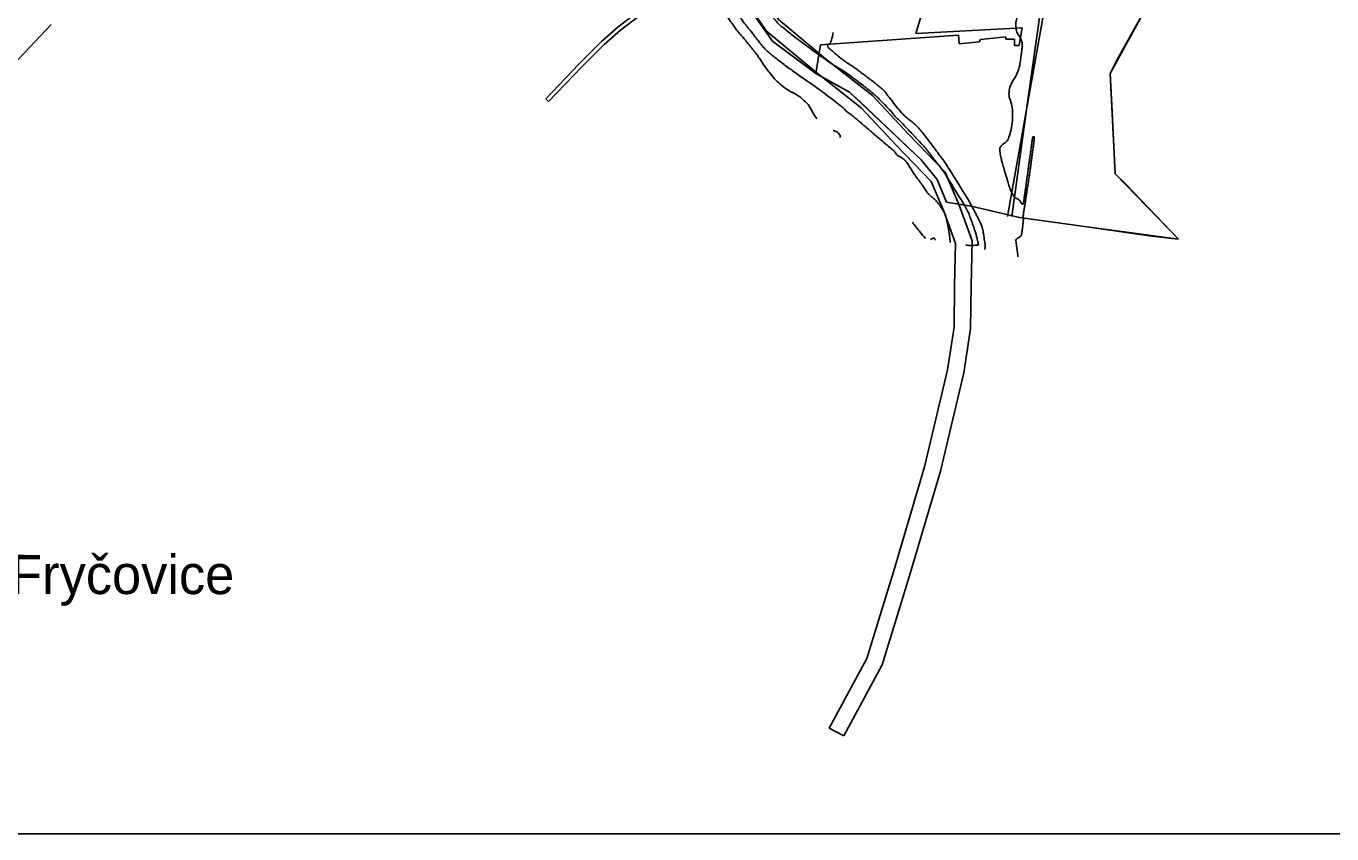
# Model space of a CAD drawing. Extents: x -478495 to -472450, y -1118050 to -1113745.
# Drawn here: x -476461 to -475794, y -1118000 to -1117588 of the extents above; entities that cross this region are included whole.
import ezdxf

# ---------------------------------------------------------------- set-up
doc = ezdxf.new("R2010")
doc.units = 0
for name, color, linetype in [('cyklostezka', 7, 'Continuous'), ('el vedeni_VVN', 7, 'Continuous'), ('hranice kú', 7, 'Continuous'), ('Implicitní', 7, 'Continuous'), ('nesmenovane pozemky', 7, 'Continuous'), ('ObPÚ', 7, 'Continuous'), ('okolní k_ú_', 7, 'Continuous'), ('silnice', 7, 'Continuous'), ('vodní plochy', 7, 'Continuous'), ('Vrstevnice_hlavni', 7, 'Continuous'), ('Vrstevnice_vedlejsi', 7, 'Continuous')]:
    doc.layers.add(name, color=color, linetype=linetype)

msp = doc.modelspace()

# ---------------------------------------------------------------- linework, layer by layer
at = {"layer": 'cyklostezka'}
msp.add_lwpolyline([(-476254.27, -1116156.47), (-476222.18, -1116232.89), (-476211.78, -1116254.37), (-476202.07, -1116276.08), (-476175.63, -1116319.27), (-476155.29, -1116349.34), (-476145.57, -1116374.89), (-476134.72, -1116405.19), (-476127.72, -1116444.76), (-476107.83, -1116579.35), (-476095.96, -1116657.36), (-476085.23, -1116737.63), (-476059.24, -1116863.13), (-475998.22, -1117016.88), (-475935.51, -1117171.2), (-475924.21, -1117200.03), (-475907.82, -1117246.95), (-475900.14, -1117263), (-475894.04, -1117290.14), (-475894.94, -1117318.4), (-475960.16, -1117684.94)], dxfattribs=at)
at = {"layer": 'el vedeni_VVN'}
msp.add_line((-476448.36, -1117586.8), (-476554.56, -1117699.16), dxfattribs=at)
at = {"layer": 'hranice kú'}
for p, q in [((-476100.96, -1117565.49), (-476080.12, -1117595.42)), ((-475907.68, -1117611.89), (-475884.68, -1117569.79)), ((-476080.12, -1117595.42), (-476057.93, -1117611.9)), ((-476057.93, -1117611.9), (-476054.39, -1117613.81)), ((-476054.39, -1117613.81), (-476051.06, -1117615.71)), ((-476051.06, -1117615.71), (-476048.51, -1117617.05)), ((-476048.51, -1117617.05), (-476046.35, -1117618.3)), ((-475905.17, -1117663.11), (-475907.68, -1117611.89)), ((-476046.35, -1117618.3), (-476043.47, -1117619.85)), ((-476043.47, -1117619.85), (-476040.79, -1117621.32)), ((-476040.79, -1117621.32), (-476035.44, -1117626.13)), ((-476035.44, -1117626.13), (-476004.15, -1117655.95)), ((-476004.15, -1117655.95), (-475996.04, -1117665.9)), ((-475872.79, -1117696.45), (-475905.17, -1117663.11)), ((-475996.04, -1117665.9), (-475991.21, -1117677.58)), ((-475991.21, -1117677.58), (-475978.66, -1117679.6)), ((-475978.66, -1117679.6), (-475953.91, -1117685.39)), ((-475953.91, -1117685.39), (-475920.81, -1117690.04)), ((-475920.81, -1117690.04), (-475872.79, -1117696.45))]:
    msp.add_line(p, q, dxfattribs=at)
at = {"layer": 'Implicitní'}
msp.add_lwpolyline([(-472500.13, -1113795.05), (-472500.13, -1118000.05), (-478445.13, -1118000.05), (-478445.13, -1113795.05)], close=True, dxfattribs=at)
at = {"layer": 'nesmenovane pozemky'}
for p, q in [((-475903.65, -1117603.88), (-475884.68, -1117569.79)), ((-476001.83, -1117574.47), (-476006.93, -1117591.35)), ((-476006.93, -1117591.35), (-475974.97, -1117589.77)), ((-475974.97, -1117589.77), (-475952.65, -1117588.52)), ((-475952.65, -1117588.52), (-475954.12, -1117597.47)), ((-476055.59, -1117597.25), (-476057.93, -1117611.9)), ((-475985.18, -1117592.28), (-476055.59, -1117597.25)), ((-475984.86, -1117596.73), (-475985.18, -1117592.28)), ((-475974.6, -1117595.69), (-475984.86, -1117596.73)), ((-475973.88, -1117594.46), (-475974.6, -1117595.69)), ((-475960.87, -1117593.11), (-475973.88, -1117594.46)), ((-475960.87, -1117594.38), (-475960.87, -1117593.11)), ((-475956.57, -1117594.38), (-475960.87, -1117594.38)), ((-475956.57, -1117597.47), (-475956.57, -1117594.38)), ((-475954.12, -1117597.47), (-475956.57, -1117597.47)), ((-475907.68, -1117611.89), (-475903.65, -1117603.88)), ((-476057.93, -1117611.9), (-476040.79, -1117621.32)), ((-475906.89, -1117627.99), (-475907.68, -1117611.89)), ((-476040.79, -1117621.32), (-476004.15, -1117655.95)), ((-475905.17, -1117663.11), (-475906.89, -1117627.99)), ((-476004.15, -1117655.95), (-475996.04, -1117665.9)), ((-475899.66, -1117668.27), (-475905.17, -1117663.11)), ((-475996.04, -1117665.9), (-475991.21, -1117677.58)), ((-475872.79, -1117696.45), (-475899.66, -1117668.27)), ((-475991.21, -1117677.58), (-475978.66, -1117679.6)), ((-475978.66, -1117679.6), (-475966.28, -1117682.49)), ((-475966.28, -1117682.49), (-475953.91, -1117685.39)), ((-475953.91, -1117685.39), (-475920.81, -1117690.04)), ((-475920.81, -1117690.04), (-475886.4, -1117694.96)), ((-475886.4, -1117694.96), (-475872.79, -1117696.45))]:
    msp.add_line(p, q, dxfattribs=at)
at = {"layer": 'ObPÚ'}
for p, q in [((-476100.96, -1117565.49), (-476080.12, -1117595.42)), ((-476006.93, -1117591.35), (-476001.83, -1117574.47)), ((-475974.97, -1117589.77), (-476006.93, -1117591.35)), ((-475952.65, -1117588.52), (-475974.97, -1117589.77)), ((-475954.12, -1117597.47), (-475952.65, -1117588.52)), ((-476080.12, -1117595.42), (-476057.93, -1117611.9)), ((-476057.93, -1117611.9), (-476055.59, -1117597.25)), ((-476055.59, -1117597.25), (-475985.18, -1117592.28)), ((-475985.18, -1117592.28), (-475984.86, -1117596.73)), ((-475984.86, -1117596.73), (-475974.6, -1117595.69)), ((-475974.6, -1117595.69), (-475973.88, -1117594.46)), ((-475973.88, -1117594.46), (-475960.87, -1117593.11)), ((-475960.87, -1117593.11), (-475960.87, -1117594.38)), ((-475960.87, -1117594.38), (-475956.57, -1117594.38)), ((-475956.57, -1117594.38), (-475956.57, -1117597.47)), ((-475956.57, -1117597.47), (-475954.12, -1117597.47))]:
    msp.add_line(p, q, dxfattribs=at)
at = {"layer": 'silnice'}
msp.add_lwpolyline([(-475957.9, -1117684.78), (-475949.88, -1117626.62), (-475938.63, -1117546.98), (-475927.03, -1117479.27), (-475917.65, -1117429.3), (-475903.98, -1117378.32)], dxfattribs=at)
at = {"layer": 'vodní plochy'}
for p, q in [((-476195.86, -1117624.84), (-476194.41, -1117626.22)), ((-476051.11, -1117946.05), (-476043.66, -1117950.07)), ((-476051.11, -1117946.05), (-476043.66, -1117950.07))]:
    msp.add_line(p, q, dxfattribs=at)
for points in [[(-476156.31, -1117361.66), (-476163.99, -1117375.67), (-476163.99, -1117389.9), (-476152.92, -1117410.92), (-476142.3, -1117430.6), (-476130.77, -1117459.77), (-476124.44, -1117494.59), (-476117.77, -1117517.88), (-476114.89, -1117528.18), (-476108.17, -1117553.38), (-476083.32, -1117590), (-476058.35, -1117610.85), (-476034.84, -1117629.4), (-476016.76, -1117648.62), (-475999.13, -1117666.94), (-475992.57, -1117682.09), (-475986.7, -1117698.61), (-475987.15, -1117720.09), (-475987.37, -1117741.29), (-475990.76, -1117763.06), (-476002.52, -1117812.64), (-476018.34, -1117866.34), (-476031.9, -1117910.44), (-476051.11, -1117946.05)], [(-476043.66, -1117950.07), (-476024.06, -1117913.72), (-476010.24, -1117868.78), (-475994.34, -1117814.81), (-475982.46, -1117764.69), (-475978.92, -1117741.99), (-475978.69, -1117720.23), (-475978.21, -1117697.23), (-475984.7, -1117678.99), (-475991.98, -1117662.17), (-476010.63, -1117642.79), (-476029.11, -1117623.14), (-476053.02, -1117604.29), (-476076.98, -1117584.27), (-476100.37, -1117549.81), (-476106.73, -1117525.94), (-476109.64, -1117515.58), (-476116.19, -1117492.67), (-476122.6, -1117457.44), (-476134.62, -1117427.02), (-476145.46, -1117406.94), (-476155.53, -1117387.81), (-476155.53, -1117377.84), (-476148.69, -1117365.34)], [(-476194.41, -1117626.22), (-476177.46, -1117608.42), (-476166.03, -1117596.98), (-476157.76, -1117589.75), (-476151.15, -1117584.76), (-476148.59, -1117582.97), (-476108.75, -1117557.22), (-476106.47, -1117555.89)], [(-476109.8, -1117555.52), (-476149.7, -1117581.31), (-476152.33, -1117583.15), (-476159.02, -1117588.2), (-476167.39, -1117595.52), (-476178.89, -1117607.02)], [(-476178.89, -1117607.02), (-476195.86, -1117624.84)]]:
    msp.add_lwpolyline(points, dxfattribs=at)
at = {"layer": 'Vrstevnice_hlavni'}
for points in [[(-476057.44, -1117634.99), (-476057.69, -1117634.62), (-476059.41, -1117631.91), (-476061.34, -1117628.56), (-476064.03, -1117625.55), (-476067.48, -1117622.88), (-476071.7, -1117620.54), (-476075.34, -1117618), (-476078.42, -1117615.24), (-476080.92, -1117612.27), (-476083.06, -1117609.55), (-476084.83, -1117607.08), (-476086.23, -1117604.87), (-476087.53, -1117602.95), (-476088.72, -1117601.3), (-476089.82, -1117599.94), (-476090.61, -1117598.96), (-476091.09, -1117598.37), (-476091.25, -1117598.16), (-476092.2, -1117597.01), (-476093.93, -1117594.91), (-476096.46, -1117591.87), (-476098.15, -1117589.84), (-476099, -1117588.82), (-476099.01, -1117588.81), (-476099.33, -1117588.34), (-476099.98, -1117587.41), (-476100.95, -1117586.02), (-476102.07, -1117584.42), (-476103.34, -1117582.61), (-476104.78, -1117580.59), (-476106.25, -1117578.08), (-476107.76, -1117575.09), (-476109.3, -1117571.6), (-476110.35, -1117569.23), (-476110.9, -1117567.98), (-476110.95, -1117567.84), (-476111.6, -1117566.05), (-476112.86, -1117562.6), (-476114.73, -1117557.5), (-476116.04, -1117553.98), (-476116.81, -1117552.04), (-476117.02, -1117551.7), (-476117.64, -1117551.15), (-476118.66, -1117550.38), (-476120.08, -1117549.41), (-476123.25, -1117546.64), (-476128.16, -1117542.06), (-476134.81, -1117535.69), (-476139.46, -1117531.05), (-476142.12, -1117528.16), (-476142.79, -1117527), (-476143.3, -1117525.93), (-476143.66, -1117524.93), (-476143.86, -1117524), (-476144.67, -1117522.64), (-476146.08, -1117520.86), (-476148.09, -1117518.64), (-476149.82, -1117516.46), (-476151.26, -1117514.3), (-476152.42, -1117512.19), (-476153.15, -1117510.07), (-476153.47, -1117507.95), (-476153.36, -1117505.83), (-476153.29, -1117504.29), (-476153.27, -1117503.33), (-476153.29, -1117502.96), (-476153.96, -1117501.7), (-476155.3, -1117499.55), (-476157.29, -1117496.52), (-476158.79, -1117493.8), (-476159.79, -1117491.38), (-476160.29, -1117489.27), (-476160.62, -1117487.82), (-476160.79, -1117487.03), (-476160.79, -1117486.91), (-476160.79, -1117486.8), (-476160.8, -1117486.7), (-476160.81, -1117486.6), (-476161.22, -1117484.01), (-476162.05, -1117478.92), (-476163.28, -1117471.34), (-476164.14, -1117466.2), (-476164.63, -1117463.5)], [(-475971.72, -1117701.76), (-475971.61, -1117701.25), (-475971.59, -1117698.98), (-475972.08, -1117695.56), (-475972.45, -1117693.12), (-475972.7, -1117691.67), (-475972.81, -1117691.21), (-475972.99, -1117690.62), (-475973.23, -1117689.89), (-475973.54, -1117689.03), (-475974.41, -1117687.19), (-475975.85, -1117684.36), (-475977.85, -1117680.54), (-475979.53, -1117677.45), (-475980.88, -1117675.08), (-475981.89, -1117673.43), (-475983.61, -1117670.66), (-475986.04, -1117666.77), (-475989.16, -1117661.77), (-475991.49, -1117658.11), (-475993.04, -1117655.8), (-475993.79, -1117654.84), (-475995.3, -1117652.83), (-475997.59, -1117649.79), (-476000.64, -1117645.7), (-476003.17, -1117642.45), (-476005.19, -1117640.03), (-476006.69, -1117638.45), (-476008.27, -1117636.98), (-476009.95, -1117635.61), (-476011.71, -1117634.35), (-476013.98, -1117632.09), (-476016.75, -1117628.84), (-476020.03, -1117624.6), (-476022.23, -1117621.76), (-476023.34, -1117620.33), (-476023.37, -1117620.3), (-476023.49, -1117620.2), (-476023.71, -1117620.02), (-476024.04, -1117619.76), (-476024.78, -1117619.16), (-476025.93, -1117618.22), (-476027.51, -1117616.94), (-476029.12, -1117615.67), (-476030.75, -1117614.42), (-476032.42, -1117613.2), (-476034.1, -1117611.94), (-476035.81, -1117610.66), (-476037.54, -1117609.35), (-476039.11, -1117608.23), (-476040.54, -1117607.3), (-476041.81, -1117606.55), (-476043.59, -1117605.28), (-476045.89, -1117603.5), (-476048.69, -1117601.2), (-476050.65, -1117599.46), (-476051.75, -1117598.28), (-476051.99, -1117597.66), (-476051.96, -1117597.21), (-476051.64, -1117596.93), (-476051.05, -1117596.82), (-476050.5, -1117596.11), (-476050, -1117594.79), (-476049.09, -1117590.93)], [(-476045.37, -1117644.51), (-476045.96, -1117642.83), (-476047.71, -1117641.43), (-476049.11, -1117640.97)], [(-476008.67, -1117687.7), (-476004.74, -1117692.89), (-476001.98, -1117696.1)], [(-475999.44, -1117696.51), (-475998.68, -1117696.34), (-475997.53, -1117695.86), (-475997.03, -1117696.9)]]:
    msp.add_spline(points, degree=3, dxfattribs=at)
at = {"layer": 'Vrstevnice_vedlejsi'}
for points in [[(-475925.81, -1117448.34), (-475926.27, -1117450.62), (-475926.74, -1117453.03), (-475927.22, -1117455.56), (-475927.71, -1117458.22), (-475928.12, -1117460.4), (-475928.45, -1117462.08), (-475928.7, -1117463.29), (-475929.01, -1117464.76), (-475929.38, -1117466.49), (-475929.8, -1117468.49), (-475930.15, -1117470.18), (-475930.42, -1117471.57), (-475930.61, -1117472.66), (-475930.86, -1117474.2), (-475931.19, -1117476.21), (-475931.59, -1117478.69), (-475931.91, -1117480.67), (-475932.15, -1117482.18), (-475932.32, -1117483.2), (-475932.51, -1117484.34), (-475932.72, -1117485.59), (-475932.95, -1117486.96), (-475933.17, -1117488.18), (-475933.37, -1117489.26), (-475933.56, -1117490.19), (-475933.78, -1117491.18), (-475934.02, -1117492.24), (-475934.28, -1117493.36), (-475934.52, -1117494.24), (-475934.72, -1117494.87), (-475934.9, -1117495.27), (-475935.04, -1117495.61), (-475935.16, -1117495.89), (-475935.25, -1117496.11), (-475935.32, -1117496.27), (-475935.37, -1117496.37), (-475935.39, -1117496.39), (-475935.35, -1117496.51), (-475935.25, -1117496.71), (-475935.1, -1117496.99), (-475935.1, -1117497.4), (-475935.26, -1117497.94), (-475935.58, -1117498.61), (-475935.96, -1117499.97), (-475936.41, -1117502.02), (-475936.93, -1117504.77), (-475937.64, -1117508.89), (-475938.52, -1117514.38), (-475939.59, -1117521.24), (-475940.34, -1117526), (-475940.78, -1117528.65), (-475940.89, -1117529.2), (-475940.96, -1117529.61), (-475940.99, -1117529.88), (-475940.98, -1117530.01), (-475940.98, -1117530.14), (-475940.97, -1117530.29), (-475940.96, -1117530.45), (-475940.99, -1117530.58), (-475941.07, -1117530.68), (-475941.18, -1117530.75), (-475941.38, -1117530.99), (-475941.66, -1117531.39), (-475942.02, -1117531.94), (-475942.31, -1117532.51), (-475942.53, -1117533.08), (-475942.67, -1117533.66), (-475942.83, -1117534.11), (-475942.99, -1117534.43), (-475943.17, -1117534.61), (-475943.26, -1117535.05), (-475943.26, -1117535.75), (-475943.17, -1117536.69), (-475943.05, -1117537.53), (-475942.91, -1117538.26), (-475942.74, -1117538.88), (-475942.67, -1117539.51), (-475942.7, -1117540.14), (-475942.83, -1117540.77), (-475943.25, -1117541.79), (-475943.98, -1117543.19), (-475945.01, -1117544.99), (-475946.02, -1117548.38), (-475947.02, -1117553.37), (-475948.01, -1117559.96), (-475949.32, -1117565.97), (-475950.93, -1117571.41), (-475952.87, -1117576.28), (-475954.34, -1117580.4), (-475955.34, -1117583.76), (-475955.87, -1117586.39), (-475955.76, -1117588.89), (-475955.01, -1117591.29), (-475953.62, -1117593.56), (-475952.78, -1117595.73), (-475952.5, -1117597.78)], [(-475981.46, -1117699.48), (-475978.55, -1117699.62), (-475976.13, -1117699.56), (-475974.95, -1117699.27), (-475975.03, -1117698.75), (-475975.23, -1117697.81), (-475975.55, -1117696.45), (-475975.99, -1117694.67), (-475976.68, -1117692.38), (-475977.61, -1117689.58), (-475978.79, -1117686.27), (-475979.74, -1117683.74), (-475980.47, -1117682), (-475980.98, -1117681.04), (-475982.27, -1117678.84), (-475984.36, -1117675.4), (-475987.25, -1117670.73), (-475989.48, -1117667.11), (-475991.07, -1117664.55), (-475992, -1117663.05), (-475993.33, -1117661.15), (-475995.07, -1117658.83), (-475997.2, -1117656.1), (-475998.94, -1117653.86), (-476000.28, -1117652.11), (-476001.22, -1117650.84), (-476003.36, -1117648.41), (-476006.69, -1117644.82), (-476011.21, -1117640.06), (-476014.37, -1117636.77), (-476016.19, -1117634.96), (-476016.65, -1117634.63), (-476017.25, -1117634.03), (-476017.99, -1117633.17), (-476018.85, -1117632.05), (-476020.29, -1117630.42), (-476022.3, -1117628.27), (-476024.89, -1117625.61), (-476027.16, -1117623.4), (-476029.12, -1117621.64), (-476030.78, -1117620.32), (-476033, -1117618.59), (-476035.8, -1117616.45), (-476039.17, -1117613.88), (-476042.25, -1117611.68), (-476045.04, -1117609.83), (-476047.54, -1117608.35), (-476050.58, -1117606.37), (-476054.16, -1117603.91), (-476058.28, -1117600.96), (-476062.21, -1117598.08), (-476065.95, -1117595.28), (-476069.5, -1117592.56), (-476072.06, -1117590.57), (-476073.62, -1117589.31), (-476074.19, -1117588.79), (-476074.68, -1117588.4), (-476075.1, -1117588.15), (-476075.44, -1117588.03), (-476076.24, -1117587.3), (-476077.5, -1117585.94), (-476079.22, -1117583.96), (-476080.45, -1117582.53), (-476081.17, -1117581.65), (-476081.4, -1117581.33), (-476081.7, -1117580.86), (-476082.07, -1117580.26), (-476082.53, -1117579.52), (-476083.53, -1117577.81), (-476085.07, -1117575.13), (-476087.16, -1117571.49), (-476088.85, -1117568.53), (-476090.14, -1117566.24), (-476091.03, -1117564.64), (-476092.06, -1117562.71), (-476093.26, -1117560.45), (-476094.6, -1117557.85), (-476095.62, -1117555.79), (-476096.3, -1117554.27), (-476096.66, -1117553.27), (-476097.35, -1117551.32), (-476098.38, -1117548.41), (-476099.75, -1117544.54), (-476100.77, -1117541.59), (-476101.44, -1117539.54), (-476101.76, -1117538.4), (-476102.23, -1117536.61), (-476102.85, -1117534.18), (-476103.61, -1117531.1), (-476104.48, -1117527.46), (-476105.44, -1117523.26)], [(-476106.82, -1117565.14), (-476105.77, -1117567.12), (-476104.85, -1117568.95), (-476104.06, -1117570.62), (-476103.42, -1117572.13), (-476102.76, -1117573.35), (-476102.11, -1117574.28), (-476101.45, -1117574.92), (-476100.89, -1117575.71), (-476100.42, -1117576.65), (-476100.04, -1117577.74), (-476099.46, -1117578.95), (-476098.67, -1117580.27), (-476097.67, -1117581.71), (-476096.76, -1117583), (-476095.95, -1117584.16), (-476095.22, -1117585.18), (-476094.4, -1117586.27), (-476093.48, -1117587.42), (-476092.46, -1117588.65), (-476091.22, -1117590.18), (-476089.77, -1117592.02), (-476088.11, -1117594.17), (-476086.73, -1117595.94), (-476085.63, -1117597.33), (-476084.82, -1117598.33), (-476083.93, -1117599.31), (-476082.96, -1117600.26), (-476081.91, -1117601.18), (-476080.42, -1117602.41), (-476078.49, -1117603.93), (-476076.11, -1117605.76), (-476073.55, -1117607.69), (-476070.8, -1117609.72), (-476067.88, -1117611.84), (-476065.08, -1117613.83), (-476062.4, -1117615.7), (-476059.85, -1117617.43), (-476056.71, -1117619.68), (-476053, -1117622.43), (-476048.7, -1117625.68), (-476045.6, -1117628.11), (-476043.69, -1117629.72), (-476042.98, -1117630.5), (-476042.18, -1117631.23), (-476041.29, -1117631.93), (-476040.33, -1117632.59), (-476039.04, -1117633.59), (-476037.42, -1117634.91), (-476035.48, -1117636.57), (-476033.78, -1117638.02), (-476032.33, -1117639.26), (-476031.14, -1117640.28), (-476030.03, -1117641.23), (-476029.02, -1117642.11), (-476028.09, -1117642.92), (-476026.41, -1117644.34), (-476023.98, -1117646.39), (-476020.78, -1117649.06), (-476018.55, -1117651.04), (-476017.29, -1117652.33), (-476016.98, -1117652.93), (-476016.54, -1117653.45), (-476015.95, -1117653.88), (-476015.22, -1117654.22), (-476014.48, -1117654.63), (-476013.72, -1117655.1), (-476012.95, -1117655.65), (-476011.89, -1117656.88), (-476010.55, -1117658.79), (-476008.92, -1117661.38), (-476007.58, -1117663.43), (-476006.54, -1117664.93), (-476005.8, -1117665.88), (-476005.03, -1117666.9), (-476004.22, -1117667.98), (-476003.37, -1117669.13), (-476002.6, -1117670.24), (-476001.89, -1117671.3), (-476001.25, -1117672.33), (-476000.36, -1117673.39), (-475999.23, -1117674.48), (-475997.84, -1117675.6), (-475996.57, -1117676.83), (-475995.42, -1117678.18), (-475994.39, -1117679.63), (-475993.59, -1117680.83), (-475993.01, -1117681.79), (-475992.67, -1117682.49), (-475992.34, -1117683.19), (-475992, -1117683.88), (-475991.67, -1117684.56), (-475991.21, -1117686.38), (-475990.62, -1117689.32), (-475989.91, -1117693.39), (-475989.48, -1117696.56), (-475989.37, -1117698.13)], [(-475952.5, -1117597.78), (-475952.77, -1117599.72), (-475953.09, -1117602.03), (-475953.46, -1117604.7), (-475953.89, -1117607.75), (-475954.83, -1117610.85), (-475956.3, -1117614.02), (-475958.29, -1117617.24), (-475959.24, -1117620.55), (-475959.17, -1117623.93), (-475958.06, -1117627.39), (-475957.55, -1117631.34), (-475957.63, -1117635.77), (-475958.31, -1117640.68), (-475959.35, -1117644.36), (-475960.75, -1117646.79), (-475962.52, -1117647.99), (-475963.63, -1117649.31), (-475964.08, -1117650.74), (-475963.88, -1117652.29), (-475963.65, -1117653.72), (-475963.38, -1117655.02), (-475963.1, -1117656.2), (-475962.49, -1117658.41), (-475961.57, -1117661.63), (-475960.34, -1117665.88), (-475959.34, -1117669.07), (-475958.59, -1117671.21), (-475958.07, -1117672.3), (-475957.63, -1117673.21), (-475957.28, -1117673.94), (-475957, -1117674.5), (-475956.52, -1117675.02), (-475955.82, -1117675.51), (-475954.9, -1117675.96), (-475954.17, -1117676.46), (-475953.64, -1117677.01), (-475953.28, -1117677.62), (-475953.01, -1117678.05), (-475952.82, -1117678.28), (-475952.72, -1117678.32), (-475952.6, -1117678.38), (-475952.48, -1117678.45), (-475952.35, -1117678.54), (-475952.26, -1117678.61), (-475952.19, -1117678.66), (-475952.15, -1117678.7), (-475952.11, -1117678.66), (-475952.07, -1117678.53), (-475952.03, -1117678.31), (-475951.98, -1117678.04), (-475951.92, -1117677.71), (-475951.86, -1117677.32), (-475951.73, -1117676.47), (-475951.54, -1117675.16), (-475951.28, -1117673.39), (-475951.02, -1117671.58), (-475950.76, -1117669.73), (-475950.5, -1117667.85), (-475950.26, -1117666.12), (-475950.04, -1117664.54), (-475949.85, -1117663.13), (-475949.67, -1117661.81), (-475949.5, -1117660.6), (-475949.36, -1117659.48), (-475949.11, -1117657.66), (-475948.77, -1117655.12), (-475948.32, -1117651.88), (-475947.98, -1117649.41), (-475947.75, -1117647.71), (-475947.62, -1117646.8), (-475947.53, -1117646.07), (-475947.46, -1117645.53), (-475947.42, -1117645.17), (-475947.36, -1117644.86), (-475947.3, -1117644.61), (-475947.21, -1117644.42), (-475947.15, -1117644.28), (-475947.1, -1117644.2), (-475947.06, -1117644.17), (-475946.98, -1117644.15), (-475946.85, -1117644.13), (-475946.67, -1117644.11), (-475946.54, -1117644.09), (-475946.47, -1117644.09), (-475946.45, -1117644.1), (-475946.45, -1117644.17), (-475946.44, -1117644.29), (-475946.45, -1117644.47), (-475946.48, -1117644.99), (-475946.56, -1117645.83), (-475946.67, -1117647.01), (-475946.78, -1117648.06), (-475946.9, -1117649), (-475947.01, -1117649.81), (-475947.2, -1117651.11), (-475947.45, -1117652.9)], [(-475947.45, -1117652.9), (-475947.76, -1117655.19), (-475948, -1117656.98), (-475948.17, -1117658.29), (-475948.26, -1117659.12), (-475948.36, -1117659.93), (-475948.46, -1117660.72), (-475948.57, -1117661.5), (-475948.82, -1117663.11), (-475949.2, -1117665.55), (-475949.71, -1117668.82), (-475950.1, -1117671.31), (-475950.36, -1117673.03), (-475950.49, -1117673.98), (-475950.66, -1117675.15), (-475950.86, -1117676.55), (-475951.1, -1117678.17), (-475951.3, -1117679.47), (-475951.47, -1117680.45), (-475951.61, -1117681.11), (-475951.74, -1117681.86), (-475951.86, -1117682.69), (-475951.97, -1117683.6), (-475952.05, -1117684.33), (-475952.1, -1117684.85), (-475952.12, -1117685.19), (-475952.11, -1117685.47), (-475952.06, -1117685.7), (-475951.99, -1117685.88), (-475952.04, -1117686.84), (-475952.22, -1117688.57), (-475952.52, -1117691.08), (-475952.75, -1117692.85), (-475952.9, -1117693.89), (-475952.97, -1117694.19), (-475953.11, -1117694.5), (-475953.32, -1117694.82), (-475953.59, -1117695.14), (-475953.98, -1117695.46), (-475954.5, -1117695.75), (-475955.15, -1117696.03), (-475955.57, -1117696.38), (-475955.78, -1117696.82), (-475955.78, -1117697.33), (-475955.46, -1117699.87), (-475954.83, -1117704.42), (-475954.68, -1117705.48)]]:
    msp.add_spline(points, degree=3, dxfattribs=at)

# ---------------------------------------------------------------- texts
at = {"layer": 'okolní k_ú_'}
msp.add_text('k.ú. Fryčovice', height=20, rotation=359.96189, dxfattribs=at).set_placement((-476519.81, -1117877.55))

doc.saveas('drawing.dxf')
